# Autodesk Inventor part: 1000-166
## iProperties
Created: 2007-03
Part Number: 1000-166
Document SubType Name: Modeling
Designer: Andy Moles
Material: Steel
Mass: 38.0546 g
Surface Area: 29.7473 cm^2
Volume: 4.84772 cm^3
Density: 7.85 g/cm^3
Author: Andy Moles
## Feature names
1. Base1
